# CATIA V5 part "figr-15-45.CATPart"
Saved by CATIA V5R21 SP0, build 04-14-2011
Part number: Part1
Bounding box of the stored display mesh (mm): x 0 to 69.121, y -21.475 to 20.775, z 0 to 47.185
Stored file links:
  D:\CATIA V5R21 E-RESOURCES\CATIA-V5R21\catia-v5r21-Prts\c15_catia_v5r21_prt\figr-15-45.CATPart
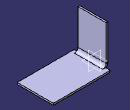
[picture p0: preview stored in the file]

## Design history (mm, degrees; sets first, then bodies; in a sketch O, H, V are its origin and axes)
SheetMetalParameters1: Thickness 2, BendRadius 4, KFactor 0.400515 {= log(min(100,max(20*SheetMetalParameters1.BendRadius,SheetMetalParameters1.Thickness)/SheetMetalParameters1.Thickness))/log(100)/2}, ReliefRadialLength 1, ReliefAxialLength 2, MinimumBendRadius 0
Body1 (main body)
  Sketch1 on xy-plane, origin (0, 0, 0), H (1, 0, 0), V (0, 1, 0)
    line L1 (2.4998, 20.7748) -> (69.1212, 20.7748)
    line L2 (69.1212, 20.7748) -> (69.1212, -21.4753)
    line L3 (69.1212, -21.4753) -> (2.4998, -21.4753)
    line L4 (2.4998, -21.4753) -> (2.4998, 20.7748)
    horizontal: L1 H, L3 H
    vertical: L2 V, L4 V
  Wall1: Thickness 2, Profile Sketch1
  Sketch2 on yz-plane, origin (0, 0, 0), H (0, 1, 0), V (0, 0, 1)
    line L1 (-17.3994, 47.1851) -> (15.4124, 47.1851)
    line L2 (15.4124, 47.1851) -> (15.4124, 3.5135)
    line L3 (15.4124, 3.5135) -> (-17.3994, 3.5135)
    line L4 (-17.3994, 3.5135) -> (-17.3994, 47.1851)
    horizontal: L1 H, L3 H
    vertical: L2 V, L4 V
  Wall2: Thickness 2, Profile Sketch2
  d_Bend1: Bend_BendTable SheetMetalParameters1, Bend_Thickness 2, Bend_KFactor 0.400515 {= log(min(100,max(20*d_Bend1.Bend_KFactorRadius,SheetMetalParameters1.Thickness)/SheetMetalParameters1.Thickness))/log(100)/2}, Bend_FirstSupport Wall1, Bend_SecondSupport Wall2, Bend_KFactorRadius 4 {= d_Bend1.CylindricalBendSurf_Radius}, Bend_Deduction -4.4586 {= (d_Bend1.CylindricalBendSurf_Radius+SheetMetalParameters1.Thickness*d_Bend1.Bend_KFactor)*(PI-abs(d_Bend1.BendSurf_OpenAngle))-2*(d_Bend1.CylindricalBendSurf_Radius+SheetMetalParameters1.Thickness)*tan(min((PI-abs(d_Bend1.BendSurf_OpenAngle)),(PI/2))/2)}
